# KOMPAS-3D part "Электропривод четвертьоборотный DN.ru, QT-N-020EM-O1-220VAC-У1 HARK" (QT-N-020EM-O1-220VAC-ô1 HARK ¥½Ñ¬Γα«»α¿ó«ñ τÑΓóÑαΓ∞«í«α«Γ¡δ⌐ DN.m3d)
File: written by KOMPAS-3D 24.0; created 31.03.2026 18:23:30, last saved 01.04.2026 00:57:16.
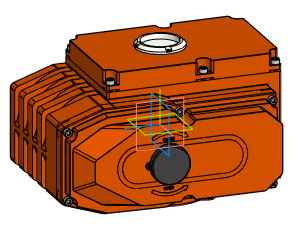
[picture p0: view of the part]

Document properties: Автор: DN.RU; Полное имя файла: D:\PROJECT CAD\DN.RU\...195\Исходники\220В\QT-N-020EM-O1-220VAC-У1 HARK Электропривод четвертьоборотный DN.ru\QT-N-020EM-O1-220VAC-У1 HARK Электропривод четвертьоборотный DN.m3d

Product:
- Body: Твердое тело1  | qty 1
    Масса: 37.407802
- Part/product: Электропривод четвертьоборотный DN.ru  | designation QT-N-020EM-O1-220VAC-У1 HARK
    Масса: 8.9
    Раздел спецификации: Прочие изделия
    Комментарий: D300-05871
    Примечание: D300-05870
    additional columns: Сталь

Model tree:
1. Твердое тело1  (labels: Твердое тело1)

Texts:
  QT-N-020EM-O1-220VAC-У1 HARK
